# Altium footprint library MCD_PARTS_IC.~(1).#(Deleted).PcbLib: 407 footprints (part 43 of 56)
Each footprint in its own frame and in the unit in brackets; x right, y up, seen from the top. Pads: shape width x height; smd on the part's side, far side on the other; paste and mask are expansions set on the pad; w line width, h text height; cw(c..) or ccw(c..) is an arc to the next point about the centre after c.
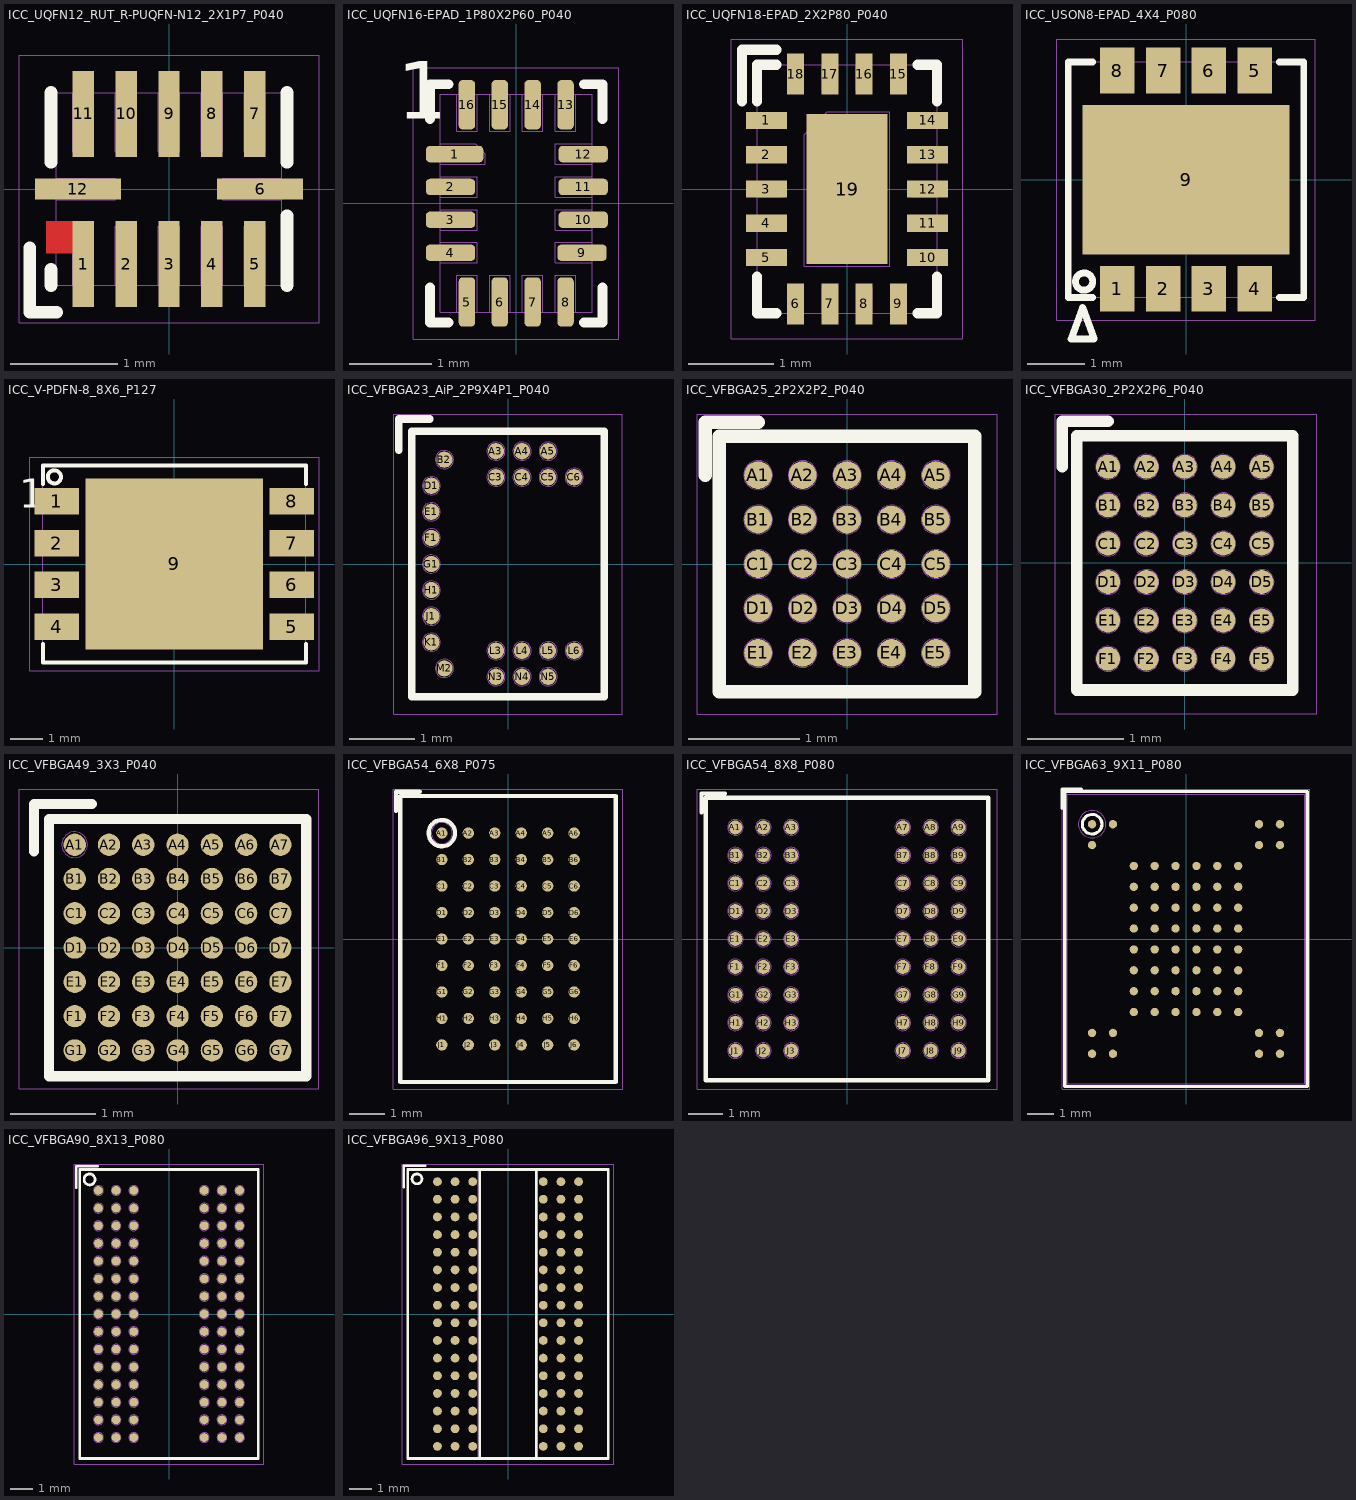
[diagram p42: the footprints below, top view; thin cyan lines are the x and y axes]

## ICC_UQFN12_RUT_R-PUQFN-N12_2X1P7_P040 [mm] "MCD-02643"
height 0.55
pads (12):
  rect 0.2x0.8 smd mask+0.05: 1(-0.8,-0.7) 2(-0.4,-0.7) 3(0,-0.7) 4(0.4,-0.7) 5(0.8,-0.7) 7(0.8,0.7) 8(0.4,0.7) 9(0,0.7) 10(-0.4,0.7) 11(-0.8,0.7)
  rect 0.8x0.2 smd mask+0.05: 6(0.85,0) 12(-0.85,0)
Top Layer:
  rectangle: -1.15,-0.6 -0.725,-0.3
Top Overlay:
  lines w0.12: -1.3,-0.55 -1.3,-1.15 -1.05,-1.15 ; -1.1,-0.9 -1.1,-0.75 ; -1.1,0.25 -1.1,0.9 ; 1.1,-0.9 1.1,-0.25 ; 1.1,0.25 1.1,0.9
M14-Top Assembly:
  lines w0.01: -1.05,-0.55 -0.9,-0.55 -0.9,-0.9 ; -1.05,-0.35 -0.7,-0.35 -0.7,-0.9 ; -1.05,-0.1 -0.5,-0.1 -0.5,0.1 -1.05,0.1 ; -0.9,0.9 -0.9,0.35 -0.7,0.35 -0.7,0.9 ; -0.5,-0.9 -0.5,-0.35 -0.3,-0.35 -0.3,-0.9 ; -0.5,0.9 -0.5,0.35 -0.3,0.35 -0.3,0.9 ; -0.1,-0.9 -0.1,-0.35 0.1,-0.35 0.1,-0.9 ; -0.1,0.9 -0.1,0.35 0.1,0.35 0.1,0.9 ; 0.3,-0.9 0.3,-0.35 0.5,-0.35 0.5,-0.9 ; 0.3,0.9 0.3,0.35 0.5,0.35 0.5,0.9 ; 0.7,-0.9 0.7,-0.35 0.9,-0.35 0.9,-0.9 ; 0.7,0.9 0.7,0.35 0.9,0.35 0.9,0.9 ; 1.05,0 1.05,-0.1 0.5,-0.1 0.5,0.1 1.05,0.1 ; -1.05,-0.9 1.05,-0.9 1.05,0.9 -1.05,0.9 -1.05,-0.9
  text "12" at -0.629,-0.213 h0.5
  text "11" at -0.983,0.479 h0.5
  text "7" at 0.696,0.484 h0.5
  text "6" at 0.948,-0.104 h0.5
  text "5" at 0.696,-0.798 h0.5
  text "1" at -0.859,-0.8 h0.5
  text "'.Designator'" at -2,-0.5 h0.75
M16-Top Courtyard:
  lines w0.01: -1.4,-1.25 1.4,-1.25 1.4,1.25 -1.4,1.25 -1.4,-1.25
3D body: height 0.13, standoff 0, extent -1.1,-0.1 -1.05,0.1
3D body: height 0.08, standoff 0, extent -1.1,-0.55 -1.05,-0.35
3D body: height 0.05, standoff 0, extent -1.1,-0.55 -0.9,-0.35
3D body: height 0.05, standoff 0, extent -0.9,-0.95 -0.7,-0.35
3D body: height 0.13, standoff 0, extent -0.9,-0.95 -0.7,-0.9
3D body: height 0.05, standoff 0, extent -0.9,0.35 -0.7,0.95
3D body: height 0.13, standoff 0, extent -0.9,0.9 -0.7,0.95
3D body: height 0.05, standoff 0, extent -1.1,-0.1 -0.5,0.1
3D body: height 0.13, standoff 0, extent -0.5,-0.95 -0.3,-0.9
3D body: height 0.05, standoff 0, extent -0.5,0.35 -0.3,0.95
3D body: height 0.13, standoff 0, extent -0.5,0.9 -0.3,0.95
3D body: height 0.05, standoff 0, extent -0.5,-0.95 -0.3,-0.35
3D body: height 0.13, standoff 0, extent -0.1,0.9 0.1,0.95
3D body: height 0.05, standoff 0, extent -0.1,-0.95 0.1,-0.35
3D body: height 0.05, standoff 0, extent -0.1,0.35 0.1,0.95
3D body: height 0.13, standoff 0, extent -0.1,-0.95 0.1,-0.9
3D body: height 0.05, standoff 0, extent 0.3,-0.95 0.5,-0.35
3D body: height 0.13, standoff 0, extent 0.3,-0.95 0.5,-0.9
3D body: height 0.13, standoff 0, extent 0.7,-0.95 0.9,-0.9
3D body: height 0.05, standoff 0, extent 0.7,-0.95 0.9,-0.35
3D body: height 0.13, standoff 0, extent 1.05,-0.1 1.1,0.1
3D body: height 0.05, standoff 0, extent 0.5,-0.1 1.1,0.1
3D body: height 0.05, standoff 0, extent 0.3,0.35 0.5,0.95
3D body: height 0.05, standoff 0, extent 0.7,0.35 0.9,0.95
3D body: height 0.13, standoff 0, extent 0.3,0.9 0.5,0.95
3D body: height 0.13, standoff 0, extent 0.7,0.9 0.9,0.95
3D body: height 0.55, standoff 0.05, extent -1.05,-0.9 1.05,0.9
3D body: height 0.56, standoff 0.55, extent -0.95,-0.8 -0.5,-0.35

## ICC_UQFN16-EPAD_1P80X2P60_P040 [mm]
height 0.55
pads (16):
  rrect50% 0.7x0.2 smd mask+0.05: 1(-0.75,0.6)
  rrect50% 0.6x0.2 smd mask+0.05: 2(-0.8,0.2) 3(-0.8,-0.2) 4(-0.8,-0.6) 9(0.8,-0.6) 10(0.815,-0.2) 11(0.815,0.2) 12(0.815,0.6)
  rrect50% 0.2x0.6 smd mask+0.05: 5(-0.6,-1.2) 6(-0.2,-1.2) 7(0.2,-1.2) 8(0.6,-1.2) 13(0.6,1.2) 14(0.2,1.2) 15(-0.2,1.2) 16(-0.6,1.2)
Top Overlay:
  lines w0.12: -1.05,-1.025 -1.05,-1.45 -0.825,-1.45 ; -1.05,1.025 -1.05,1.45 -0.825,1.45 ; 0.825,-1.45 1.05,-1.45 1.05,-1.025 ; 0.825,1.45 1.05,1.45 1.05,1.025
  text "1" at -1.45,0.8 h1.2
M14-Top Assembly:
  lines w0.01: -0.925,-0.725 -0.475,-0.725 -0.475,-0.475 -0.925,-0.475 ; -0.925,-0.325 -0.475,-0.325 -0.475,-0.075 -0.925,-0.075 ; -0.925,0.075 -0.475,0.075 -0.475,0.325 -0.925,0.325 ; -0.925,0.475 -0.375,0.475 -0.375,0.6 -0.5,0.725 -0.925,0.725 ; -0.725,-1.325 -0.725,-0.875 -0.475,-0.875 -0.475,-1.325 ; -0.725,1.325 -0.725,0.875 -0.475,0.875 -0.475,1.325 ; -0.325,-1.325 -0.325,-0.875 -0.075,-0.875 -0.075,-1.325 ; -0.325,1.325 -0.325,0.875 -0.075,0.875 -0.075,1.325 ; 0.075,-1.325 0.075,-0.875 0.325,-0.875 0.325,-1.325 ; 0.075,1.325 0.075,0.875 0.325,0.875 0.325,1.325 ; 0.475,-1.325 0.475,-0.875 0.725,-0.875 0.725,-1.325 ; 0.475,1.325 0.475,0.875 0.725,0.875 0.725,1.325 ; 0.925,-0.725 0.475,-0.725 0.475,-0.475 0.925,-0.475 ; 0.925,-0.325 0.475,-0.325 0.475,-0.075 0.925,-0.075 ; 0.925,0.075 0.475,0.075 0.475,0.325 0.925,0.325 ; 0.925,0.475 0.475,0.475 0.475,0.725 0.925,0.725 ; -1.05,1.45 -1.05,1.45 ; -1.05,1.45 -1.05,1.45 ; -1.05,-1.45 -1.05,-1.45 ; -0.925,-1.325 -0.925,1.325 0.925,1.325 0.925,-1.325 -0.925,-1.325
  text "13" at 0.425,0.975 h0.4
  text "16" at -0.775,0.975 h0.4
  text "8" at 0.525,-1.225 h0.4
  text "4" at -0.875,-0.725 h0.4
  text "12" at 0.525,0.475 h0.4
  text "9" at 0.7,-0.725 h0.4
  text "5" at -0.694,-1.221 h0.4
  text "1" at -0.844,0.475 h0.4
  text "'.Designator'" at -2,-0.5 h0.75
M16-Top Courtyard:
  lines w0.01: -1.25,-1.65 -1.25,1.65 1.25,1.65 1.25,-1.65 -1.25,-1.65
3D body "User Library-UQFN-16-0_4(Case 2_6mmx1_8mm Height 0_55mm).STEP": height 0.56, standoff 0, extent -0.91,-1.31 0.91,1.31

## ICC_UQFN18-EPAD_2X2P80_P040 [mm] "MCD-02300"
height 0.4
pads (19):
  rect 0.48x0.2 smd mask+0.05: 1(-0.94,0.8) 2(-0.94,0.4) 3(-0.94,0) 4(-0.94,-0.4) 5(-0.94,-0.8) 10(0.94,-0.8) 11(0.94,-0.4) 12(0.94,0) 13(0.94,0.4) 14(0.94,0.8)
  rect 0.2x0.48 smd mask+0.05: 6(-0.6,-1.34) 7(-0.2,-1.34) 8(0.2,-1.34) 9(0.6,-1.34) 15(0.6,1.34) 16(0.2,1.34) 17(-0.2,1.34) 18(-0.6,1.34)
  rect 0.95x1.75 smd mask+0.05: 19(0,0)
Top Overlay:
  lines w0.12: -1.225,1.025 -1.225,1.625 -0.825,1.625 ; -1.05,-1.025 -1.05,-1.45 -0.825,-1.45 ; -1.05,1.025 -1.05,1.45 -0.825,1.45 ; 0.825,-1.45 1.05,-1.45 1.05,-1.025 ; 0.825,1.45 1.05,1.45 1.05,1.025
M14-Top Assembly:
  lines w0.01: -1.05,-0.89 -0.75,-0.89 -0.75,-0.71 -1.05,-0.71 ; -1.05,-0.49 -0.75,-0.49 -0.75,-0.31 -1.05,-0.31 ; -1.05,-0.09 -0.75,-0.09 -0.75,0.09 -1.05,0.09 ; -1.05,0.31 -0.75,0.31 -0.75,0.49 -1.05,0.49 ; -1.05,0.71 -0.75,0.71 -0.75,0.89 -1.05,0.89 ; -0.69,1.45 -0.69,1.15 -0.51,1.15 -0.51,1.45 ; -0.687,-1.45 -0.687,-1.15 -0.507,-1.15 -0.507,-1.45 ; -0.29,1.45 -0.29,1.15 -0.11,1.15 -0.11,1.45 ; -0.287,-1.45 -0.287,-1.15 -0.107,-1.15 -0.107,-1.45 ; 0.11,1.45 0.11,1.15 0.29,1.15 0.29,1.45 ; 0.113,-1.45 0.113,-1.15 0.293,-1.15 0.293,-1.45 ; 0.51,1.45 0.51,1.15 0.69,1.15 0.69,1.45 ; 0.513,-1.45 0.513,-1.15 0.693,-1.15 0.693,-1.45 ; 1.05,-0.89 0.75,-0.89 0.75,-0.71 1.05,-0.71 ; 1.05,-0.49 0.75,-0.49 0.75,-0.31 1.05,-0.31 ; 1.05,-0.09 0.75,-0.09 0.75,0.09 1.05,0.09 ; 1.05,0.31 0.75,0.31 0.75,0.49 1.05,0.49 ; 1.05,0.71 0.75,0.71 0.75,0.89 1.05,0.89 ; -1.05,-1.45 1.05,-1.45 1.05,1.45 -1.05,1.45 ; -1.05,-1.45 -1.05,-1.45 ; -1.05,-1.45 -1.05,1.45 ; -1.05,1.45 -1.05,1.45 ; -1.05,1.45 -1.05,1.45 ; -0.5,-0.9 0.5,-0.9 0.5,0.9 -0.23,0.9 -0.5,0.63 -0.5,-0.9
  text "'.Designator'" at -1.803,-0.619 h0.75
  text "1" at -0.95,0.685 h0.4
  text "5" at -1,-0.915 h0.4
  text "10" at 0.675,-0.915 h0.4
  text "14" at 0.675,0.675 h0.4
  text "6" at -0.687,-1.425 h0.4
  text "9" at 0.513,-1.425 h0.4
  text "18" at -0.763,1.162 h0.4
  text "15" at 0.425,1.162 h0.4
  text "19" at -0.175,0.262 h0.4
M16-Top Courtyard:
  lines w0.01: -1.35,-1.75 1.35,-1.75 1.35,-1.725 1.35,1.725 1.35,1.75 -1.35,1.75 -1.35,1.725 -1.35,-1.725 -1.35,-1.75
3D body: height 0.41, standoff 0.4, extent -0.925,1.075 -0.675,1.325
3D body: height 0.05, standoff 0, extent -0.5,-0.9 0.5,0.9
3D body: height 0.4, standoff 0.05, extent -1.05,-1.45 1.05,1.45
3D body: height 0.05, standoff 0, extent 0.75,0.71 1.05,0.89
3D body: height 0.15, standoff 0, extent 1.05,0.71 1.1,0.89
3D body: height 0.05, standoff 0, extent 0.75,0.31 1.05,0.49
3D body: height 0.15, standoff 0, extent 1.05,0.31 1.1,0.49
3D body: height 0.05, standoff 0, extent 0.75,-0.09 1.05,0.09
3D body: height 0.15, standoff 0, extent 1.05,-0.09 1.1,0.09
3D body: height 0.05, standoff 0, extent 0.75,-0.49 1.05,-0.31
3D body: height 0.15, standoff 0, extent 1.05,-0.49 1.1,-0.31
3D body: height 0.05, standoff 0, extent 0.75,-0.89 1.05,-0.71
3D body: height 0.15, standoff 0, extent 1.05,-0.89 1.1,-0.71
3D body: height 0.05, standoff 0, extent 0.512,-1.45 0.692,-1.15
3D body: height 0.15, standoff 0, extent 0.512,-1.5 0.693,-1.45
3D body: height 0.05, standoff 0, extent 0.112,-1.45 0.292,-1.15
3D body: height 0.15, standoff 0, extent 0.112,-1.5 0.292,-1.45
3D body: height 0.05, standoff 0, extent -0.288,-1.45 -0.108,-1.15
3D body: height 0.15, standoff 0, extent -0.288,-1.5 -0.108,-1.45
3D body: height 0.05, standoff 0, extent -0.688,-1.45 -0.508,-1.15
3D body: height 0.15, standoff 0, extent -0.688,-1.5 -0.507,-1.45
3D body: height 0.05, standoff 0, extent -1.05,-0.89 -0.75,-0.71
3D body: height 0.15, standoff 0, extent -1.1,-0.89 -1.05,-0.71
3D body: height 0.05, standoff 0, extent -1.05,-0.49 -0.75,-0.31
3D body: height 0.15, standoff 0, extent -1.1,-0.49 -1.05,-0.31
3D body: height 0.05, standoff 0, extent -1.05,-0.09 -0.75,0.09
3D body: height 0.15, standoff 0, extent -1.1,-0.09 -1.05,0.09
3D body: height 0.05, standoff 0, extent -1.05,0.31 -0.75,0.49
3D body: height 0.15, standoff 0, extent -1.1,0.31 -1.05,0.49
3D body: height 0.05, standoff 0, extent -1.05,0.71 -0.75,0.89
3D body: height 0.15, standoff 0, extent -1.1,0.71 -1.05,0.89
3D body: height 0.05, standoff 0, extent 0.51,1.15 0.69,1.45
3D body: height 0.15, standoff 0, extent 0.51,1.45 0.69,1.5
3D body: height 0.05, standoff 0, extent 0.11,1.15 0.29,1.45
3D body: height 0.15, standoff 0, extent 0.11,1.45 0.29,1.5
3D body: height 0.05, standoff 0, extent -0.29,1.15 -0.11,1.45
3D body: height 0.15, standoff 0, extent -0.29,1.45 -0.11,1.5
3D body: height 0.05, standoff 0, extent -0.69,1.15 -0.51,1.45
3D body: height 0.15, standoff 0, extent -0.69,1.45 -0.51,1.5

## ICC_USON8-EPAD_4X4_P080 [mm]
height 0.6
pads (9):
  rect 0.6x0.8 smd paste+0 mask+0.05: 1(-1.2,-1.9) 2(-0.4,-1.9) 3(0.4,-1.9) 4(1.2,-1.9) 5(1.2,1.9) 6(0.4,1.9) 7(-0.4,1.9) 8(-1.2,1.9)
  rect 3.6x2.6 smd paste+0 mask+0.05: 9(0,0)
Top Overlay:
  circle w0.12: c-1.775,-1.775 r0.15
  lines w0.12: -1.625,-2.05 -2.05,-2.05 -2.05,2.05 -1.625,2.05 ; 1.625,-2.05 2.05,-2.05 2.05,2.05 1.625,2.05 ; -2,-2.775 -1.6,-2.775 -1.8,-2.225 -2,-2.775
M14-Top Assembly:
  lines w0.01: -1.375,-2.05 -1.375,-1.6 -1.025,-1.6 -1.025,-2.05 ; -1.375,2.05 -1.375,1.6 -1.025,1.6 -1.025,2.05 ; -0.575,-2.05 -0.575,-1.6 -0.225,-1.6 -0.225,-2.05 ; -0.575,2.05 -0.575,1.6 -0.225,1.6 -0.225,2.05 ; 0.225,-2.05 0.225,-1.6 0.575,-1.6 0.575,-2.05 ; 0.225,2.05 0.225,1.6 0.575,1.6 0.575,2.05 ; 1.025,-2.05 1.025,-1.6 1.375,-1.6 1.375,-2.05 ; 1.025,2.05 1.025,1.6 1.375,1.6 1.375,2.05 ; -2.05,-2.05 2.05,-2.05 2.05,2.05 -2.05,2.05 -2.05,-2.05 ; -1.55,-1.2 1.55,-1.2 1.55,1.2 -1.55,1.2 -1.55,-1.2
  text "'.Designator'" at -2,0.25 h0.75
  text "1" at -1.6,-2 h0.7
  text "4" at 1.425,-2 h0.7
  text "5" at 1.425,1.55 h0.7
  text "8" at -1.725,1.55 h0.7
  text "9" at -0.125,-0.2 h0.7
M16-Top Courtyard:
  lines w0.01: -2.25,-2.45 2.25,-2.45 2.25,2.45 -2.25,2.45 -2.25,-2.45
3D body: height 0.6, standoff 0, extent -2.05,-2.05 2.05,2.05
3D body "USON_8_4X4.STEP": height 0.59, standoff 0, extent -2,-2 2,2

## ICC_V-PDFN-8_8X6_P127 [mm]
height 1
pads (9):
  rect 1.35x0.8 smd mask+0.05: 1(-3.575,1.905) 2(-3.575,0.635) 3(-3.575,-0.635) 4(-3.575,-1.905) 5(3.575,-1.905) 6(3.575,-0.635) 7(3.575,0.635) 8(3.575,1.905)
  rect 5.4x5.2 smd mask+0.05: 9(0,0)
Top Overlay:
  circle w0.12: c-3.65,2.65 r0.2
  lines w0.12: -4,-2.425 -4,-3 4,-3 4,-2.425 ; -4,2.425 -4,3 4,3 4,2.425
  text "1" at -4.725,1.425 h1.5
M14-Top Assembly:
  circle w0.01: c-3.675,2.675 r0.2
  lines w0.01: -4,-2.16 -3.4,-2.16 -3.4,-1.65 -4,-1.65 ; -4,-0.89 -3.4,-0.89 -3.4,-0.38 -4,-0.38 ; -4,0.38 -3.4,0.38 -3.4,0.89 -4,0.89 ; -4,1.65 -3.4,1.65 -3.4,2.16 -4,2.16 ; 4,-2.16 3.4,-2.16 3.4,-1.65 4,-1.65 ; 4,-0.89 3.4,-0.89 3.4,-0.38 4,-0.38 ; 4,0.38 3.4,0.38 3.4,0.89 4,0.89 ; 4,1.65 3.4,1.65 3.4,2.16 4,2.16 ; -4,-3 -4,3 4,3 4,-3 -4,-3 ; -2.6,-2.4 -2.6,2.4 2.6,2.4 2.6,-2.4 -2.6,-2.4
  text "1" at -3.325,1.45 h1.5
  text "4" at -3.325,-2.375 h1.5
  text "5" at 2.675,-2.375 h1.5
  text "8" at 2.675,1.425 h1.5
  text "'.Designator'" at -2,-0.5 h0.75
M16-Top Courtyard:
  lines w0.01: -4.4,-3.25 4.4,-3.25 4.4,3.25 -4.4,3.25 -4.4,3.05 -4.4,-3.25
3D body: height 1, standoff 0, extent -4.005,-3.005 4.005,3.005
3D body "V-PDFN-8_8X6_.STEP": height 1.01, standoff 0, extent -4.025,-2.997 4.025,3.003

## ICC_VFBGA23_AiP_2P9X4P1_P040 [mm] "MCD-03321"
height 0.8
pads (23):
  round 0.25 smd mask+0.038: A3(-0.185,1.73) A4(0.215,1.73) A5(0.615,1.73) B2(-0.975,1.6) C3(-0.185,1.33) C4(0.215,1.33) C5(0.615,1.33) C6(1.015,1.33) D1(-1.175,1.2) E1(-1.175,0.8) F1(-1.175,0.4) G1(-1.175,0) H1(-1.175,-0.4) J1(-1.175,-0.8) K1(-1.175,-1.2) L3(-0.185,-1.33) L4(0.215,-1.33) L5(0.615,-1.33) L6(1.015,-1.33) M2(-0.975,-1.6) N3(-0.185,-1.73) N4(0.215,-1.73) N5(0.615,-1.73)
Top Overlay:
  lines w0.12: -1.675,1.75 -1.675,2.225 -1.2,2.225 ; -1.475,-2.035 1.475,-2.035 1.475,2.035 -1.475,2.035 -1.475,-2.035
M14-Top Assembly:
  circle w0.01: c1.015,1.33 r0.14
  circle w0.01: c0.615,1.33 r0.14
  circle w0.01: c0.215,1.33 r0.14
  circle w0.01: c-0.185,1.33 r0.14
  circle w0.01: c0.615,1.73 r0.14
  circle w0.01: c0.215,1.73 r0.14
  circle w0.01: c-0.185,1.73 r0.14
  circle w0.01: c1.015,-1.33 r0.14
  circle w0.01: c0.615,-1.33 r0.14
  circle w0.01: c0.215,-1.33 r0.14
  circle w0.01: c-0.185,-1.33 r0.14
  circle w0.01: c0.615,-1.73 r0.14
  circle w0.01: c0.215,-1.73 r0.14
  circle w0.01: c-0.185,-1.73 r0.14
  circle w0.01: c-0.975,-1.6 r0.14
  circle w0.01: c-0.975,1.6 r0.14
  circle w0.01: c-1.175,0 r0.14
  circle w0.01: c-1.175,0.4 r0.14
  circle w0.01: c-1.175,-0.4 r0.14
  circle w0.01: c-1.175,-0.8 r0.14
  circle w0.01: c-1.175,-1.2 r0.14
  circle w0.01: c-1.175,0.8 r0.14
  circle w0.01: c-1.175,1.2 r0.14
  lines w0.01: -1.475,-2.035 -1.475,2.035 1.475,2.035 1.475,-2.035 -1.475,-2.035
  text "A3" at -0.35,1.625 h0.3
  text "'.Designator'" at -2,-0.5 h0.75
M16-Top Courtyard:
  lines w0.01: -1.75,-2.3 1.75,-2.3 1.75,2.3 -1.75,2.3 -1.75,-2.3
3D body: height 0.26, standoff -0.02, extent 0.475,-1.87 0.755,-1.59
3D body: height 0.26, standoff -0.02, extent 0.075,-1.87 0.355,-1.59
3D body: height 0.26, standoff -0.02, extent -0.325,-1.87 -0.045,-1.59
3D body: height 0.26, standoff -0.02, extent 0.875,-1.47 1.155,-1.19
3D body: height 0.26, standoff -0.02, extent 0.475,-1.47 0.755,-1.19
3D body: height 0.26, standoff -0.02, extent 0.075,-1.47 0.355,-1.19
3D body: height 0.26, standoff -0.02, extent -0.325,-1.47 -0.045,-1.19
3D body: height 0.26, standoff -0.02, extent -1.115,-1.74 -0.835,-1.46
3D body: height 0.26, standoff -0.02, extent -1.315,-1.34 -1.035,-1.06
3D body: height 0.26, standoff -0.02, extent -1.315,-0.94 -1.035,-0.66
3D body: height 0.26, standoff -0.02, extent -1.315,-0.54 -1.035,-0.26
3D body: height 0.26, standoff -0.02, extent -1.315,-0.14 -1.035,0.14
3D body: height 0.26, standoff -0.02, extent -1.315,0.26 -1.035,0.54
3D body: height 0.26, standoff -0.02, extent -1.315,0.66 -1.035,0.94
3D body: height 0.26, standoff -0.02, extent -1.315,1.06 -1.035,1.34
3D body: height 0.26, standoff -0.02, extent 0.875,1.19 1.155,1.47
3D body: height 0.26, standoff -0.02, extent 0.475,1.19 0.755,1.47
3D body: height 0.26, standoff -0.02, extent 0.075,1.19 0.355,1.47
3D body: height 0.26, standoff -0.02, extent -0.325,1.19 -0.045,1.47
3D body: height 0.26, standoff -0.02, extent -1.115,1.46 -0.835,1.74
3D body: height 0.26, standoff -0.02, extent 0.475,1.59 0.755,1.87
3D body: height 0.26, standoff -0.02, extent 0.075,1.59 0.355,1.87
3D body: height 0.26, standoff -0.02, extent -0.325,1.59 -0.045,1.87
3D body: height 0.8, standoff 0.1, extent -1.5,-2.06 1.5,2.06
3D body: height 0.81, standoff 0.8, extent -1.124,1.45 -0.825,1.75

## ICC_VFBGA25_2P2X2P2_P040 [mm] "MCD-02719"
height 1
pads (25):
  round 0.25 smd mask+0.038: A1(-0.8,0.8) A2(-0.4,0.8) A3(0,0.8) A4(0.4,0.8) A5(0.8,0.8) B1(-0.8,0.4) B2(-0.4,0.4) B3(0,0.4) B4(0.4,0.4) B5(0.8,0.4) C1(-0.8,0) C2(-0.4,0) C3(0,0) C4(0.4,0) C5(0.8,0) D1(-0.8,-0.4) D2(-0.4,-0.4) D3(0,-0.4) D4(0.4,-0.4) D5(0.8,-0.4) E1(-0.8,-0.8) E2(-0.4,-0.8) E3(0,-0.8) E4(0.4,-0.8) E5(0.8,-0.8)
Top Overlay:
  lines w0.12: -1.275,0.8 -1.275,1.275 -0.8,1.275 ; -1.15,-1.15 1.15,-1.15 1.15,1.15 -1.15,1.15 -1.15,-1.15
M14-Top Assembly:
  circle w0.01: c0.8,0.8 r0.13
  circle w0.01: c0.4,0.8 r0.13
  circle w0.01: c0.8,0.4 r0.13
  circle w0.01: c0.4,0.4 r0.13
  circle w0.01: c0.8,0 r0.13
  circle w0.01: c0.4,0 r0.13
  circle w0.01: c0,0 r0.13
  circle w0.01: c0.8,-0.4 r0.13
  circle w0.01: c0.4,-0.4 r0.13
  circle w0.01: c0.8,-0.8 r0.13
  circle w0.01: c0.4,-0.8 r0.13
  circle w0.01: c0,-0.8 r0.13
  circle w0.01: c0,-0.4 r0.13
  circle w0.01: c0,0.4 r0.13
  circle w0.01: c0,0.8 r0.13
  circle w0.01: c-0.4,0.4 r0.13
  circle w0.01: c-0.4,0 r0.13
  circle w0.01: c-0.4,-0.8 r0.13
  circle w0.01: c-0.4,-0.4 r0.13
  circle w0.01: c-0.4,0.8 r0.13
  circle w0.01: c-0.8,0.4 r0.13
  circle w0.01: c-0.8,-0.4 r0.13
  circle w0.01: c-0.8,0 r0.13
  circle w0.01: c-0.8,-0.8 r0.13
  circle w0.01: c-0.8,0.8 r0.13
  lines w0.01: -1.15,-1.15 1.15,-1.15 1.15,1.15 -1.15,1.15 -1.15,-1.15
  text "A5" at 0.66,0.71 h0.15
  text "E5" at 0.676,-0.89 h0.15
  text "A1" at -0.907,0.71 h0.15
  text "E1" at -0.892,-0.89 h0.15
  text "'.Designator'" at -2,-0.5 h0.75
M16-Top Courtyard:
  lines w0.01: -1.35,-1.35 -1.35,1.35 1.35,1.35 1.35,-1.35 -1.35,-1.35
3D body: height 0.26, standoff -0.02, extent 0.66,-0.94 0.94,-0.66
3D body: height 0.26, standoff -0.02, extent 0.26,-0.94 0.54,-0.66
3D body: height 0.26, standoff -0.02, extent -0.14,-0.94 0.14,-0.66
3D body: height 0.26, standoff -0.02, extent -0.54,-0.94 -0.26,-0.66
3D body: height 0.26, standoff -0.02, extent -0.94,-0.94 -0.66,-0.66
3D body: height 0.26, standoff -0.02, extent 0.66,-0.54 0.94,-0.26
3D body: height 0.26, standoff -0.02, extent 0.26,-0.54 0.54,-0.26
3D body: height 0.26, standoff -0.02, extent -0.14,-0.54 0.14,-0.26
3D body: height 0.26, standoff -0.02, extent -0.54,-0.54 -0.26,-0.26
3D body: height 0.26, standoff -0.02, extent -0.94,-0.54 -0.66,-0.26
3D body: height 0.26, standoff -0.02, extent 0.66,-0.14 0.94,0.14
3D body: height 0.26, standoff -0.02, extent 0.26,-0.14 0.54,0.14
3D body: height 0.26, standoff -0.02, extent -0.14,-0.14 0.14,0.14
3D body: height 0.26, standoff -0.02, extent -0.54,-0.14 -0.26,0.14
3D body: height 0.26, standoff -0.02, extent -0.94,-0.14 -0.66,0.14
3D body: height 0.26, standoff -0.02, extent 0.66,0.26 0.94,0.54
3D body: height 0.26, standoff -0.02, extent 0.26,0.26 0.54,0.54
3D body: height 0.26, standoff -0.02, extent -0.14,0.26 0.14,0.54
3D body: height 0.26, standoff -0.02, extent -0.54,0.26 -0.26,0.54
3D body: height 0.26, standoff -0.02, extent -0.94,0.26 -0.66,0.54
3D body: height 0.26, standoff -0.02, extent 0.66,0.66 0.94,0.94
3D body: height 0.26, standoff -0.02, extent 0.26,0.66 0.54,0.94
3D body: height 0.26, standoff -0.02, extent -0.14,0.66 0.14,0.94
3D body: height 0.26, standoff -0.02, extent -0.54,0.66 -0.26,0.94
3D body: height 1.01, standoff 1, extent -0.95,0.65 -0.65,0.95
3D body: height 1, standoff 0.22, extent -1.15,-1.15 1.15,1.15
3D body: height 0.26, standoff -0.02, extent -0.94,0.66 -0.66,0.94

## ICC_VFBGA30_2P2X2P6_P040 [mm] "MCD-03321"
height 0.9
pads (30):
  round 0.25 smd mask+0.038: A1(-0.8,1) A2(-0.4,1) A3(0,1) A4(0.4,1) A5(0.8,1) B1(-0.8,0.6) B2(-0.4,0.6) B3(0,0.6) B4(0.4,0.6) B5(0.8,0.6) C1(-0.8,0.2) C2(-0.4,0.2) C3(0,0.2) C4(0.4,0.2) C5(0.8,0.2) D1(-0.8,-0.2) D2(-0.4,-0.2) D3(0,-0.2) D4(0.4,-0.2) D5(0.8,-0.2) E1(-0.8,-0.6) E2(-0.4,-0.6) E3(0,-0.6) E4(0.4,-0.6) E5(0.8,-0.6) F1(-0.8,-1) F2(-0.4,-1) F3(0,-1) F4(0.4,-1) F5(0.8,-1)
Top Overlay:
  lines w0.12: -1.275,1 -1.275,1.475 -0.8,1.475 ; -1.125,-1.325 -1.125,1.325 1.125,1.325 1.125,-1.325 -1.125,-1.325
M14-Top Assembly:
  circle w0.01: c-0.8,1 r0.13
  circle w0.01: c-0.8,-0.6 r0.13
  circle w0.01: c-0.8,0.2 r0.13
  circle w0.01: c-0.8,-0.2 r0.13
  circle w0.01: c-0.8,0.6 r0.13
  circle w0.01: c-0.4,1 r0.13
  circle w0.01: c-0.4,-0.2 r0.13
  circle w0.01: c-0.4,-0.6 r0.13
  circle w0.01: c-0.4,0.2 r0.13
  circle w0.01: c-0.4,0.6 r0.13
  circle w0.01: c0,1 r0.13
  circle w0.01: c0,0.6 r0.13
  circle w0.01: c0,-0.2 r0.13
  circle w0.01: c0,-0.6 r0.13
  circle w0.01: c0.4,-0.6 r0.13
  circle w0.01: c0.8,-0.6 r0.13
  circle w0.01: c0.4,-0.2 r0.13
  circle w0.01: c0.8,-0.2 r0.13
  circle w0.01: c0,0.2 r0.13
  circle w0.01: c0.4,0.2 r0.13
  circle w0.01: c0.8,0.2 r0.13
  circle w0.01: c0.4,0.6 r0.13
  circle w0.01: c0.8,0.6 r0.13
  circle w0.01: c0.4,1 r0.13
  circle w0.01: c0.8,1 r0.13
  circle w0.01: c-0.8,-1 r0.13
  circle w0.01: c-0.4,-1 r0.13
  circle w0.01: c0,-1 r0.13
  circle w0.01: c0.4,-1 r0.13
  circle w0.01: c0.8,-1 r0.13
  lines w0.01: -1.125,-1.325 -1.125,1.325 1.125,1.325 1.125,-1.325 -1.125,-1.325
  text "'.Designator'" at -2,-0.5 h0.75
  text "A1" at -0.907,0.91 h0.15
  text "A5" at 0.66,0.91 h0.15
  text "F1" at -0.892,-1.09 h0.15
  text "F5" at 0.676,-1.09 h0.15
M16-Top Courtyard:
  lines w0.01: -1.35,-1.575 1.375,-1.575 1.375,1.55 -1.35,1.55 -1.35,-1.575
3D body: height 0.26, standoff -0.02, extent -0.94,0.86 -0.66,1.14
3D body: height 0.9, standoff 0.22, extent -1.125,-1.325 1.125,1.325
3D body: height 0.91, standoff 0.9, extent -0.949,0.85 -0.65,1.15
3D body: height 0.26, standoff -0.02, extent -0.54,0.86 -0.26,1.14
3D body: height 0.26, standoff -0.02, extent -0.14,0.86 0.14,1.14
3D body: height 0.26, standoff -0.02, extent 0.26,0.86 0.54,1.14
3D body: height 0.26, standoff -0.02, extent 0.66,0.86 0.94,1.14
3D body: height 0.26, standoff -0.02, extent -0.94,0.46 -0.66,0.74
3D body: height 0.26, standoff -0.02, extent -0.54,0.46 -0.26,0.74
3D body: height 0.26, standoff -0.02, extent -0.14,0.46 0.14,0.74
3D body: height 0.26, standoff -0.02, extent 0.26,0.46 0.54,0.74
3D body: height 0.26, standoff -0.02, extent 0.66,0.46 0.94,0.74
3D body: height 0.26, standoff -0.02, extent -0.94,0.06 -0.66,0.34
3D body: height 0.26, standoff -0.02, extent -0.54,0.06 -0.26,0.34
3D body: height 0.26, standoff -0.02, extent -0.14,0.06 0.14,0.34
3D body: height 0.26, standoff -0.02, extent 0.26,0.06 0.54,0.34
3D body: height 0.26, standoff -0.02, extent 0.66,0.06 0.94,0.34
3D body: height 0.26, standoff -0.02, extent -0.94,-0.34 -0.66,-0.06
3D body: height 0.26, standoff -0.02, extent -0.54,-0.34 -0.26,-0.06
3D body: height 0.26, standoff -0.02, extent -0.14,-0.34 0.14,-0.06
3D body: height 0.26, standoff -0.02, extent 0.26,-0.34 0.54,-0.06
3D body: height 0.26, standoff -0.02, extent 0.66,-0.34 0.94,-0.06
3D body: height 0.26, standoff -0.02, extent -0.94,-0.74 -0.66,-0.46
3D body: height 0.26, standoff -0.02, extent -0.54,-0.74 -0.26,-0.46
3D body: height 0.26, standoff -0.02, extent -0.14,-0.74 0.14,-0.46
3D body: height 0.26, standoff -0.02, extent 0.26,-0.74 0.54,-0.46
3D body: height 0.26, standoff -0.02, extent 0.66,-0.74 0.94,-0.46
3D body: height 0.26, standoff -0.02, extent -0.94,-1.14 -0.66,-0.86
3D body: height 0.26, standoff -0.02, extent -0.54,-1.14 -0.26,-0.86
3D body: height 0.26, standoff -0.02, extent -0.14,-1.14 0.14,-0.86
3D body: height 0.26, standoff -0.02, extent 0.26,-1.14 0.54,-0.86
3D body: height 0.26, standoff -0.02, extent 0.66,-1.14 0.94,-0.86

## ICC_VFBGA49_3X3_P040 [mm] "MCD-02213"
height 1
pads (49):
  round 0.26 smd mask+0.03: A1(-1.2,1.2) A2(-0.8,1.2) A3(-0.4,1.2) A4(0,1.2) A5(0.4,1.2) A6(0.8,1.2) A7(1.2,1.2) B1(-1.2,0.8) B2(-0.8,0.8) B3(-0.4,0.8) B4(0,0.8) B5(0.4,0.8) B6(0.8,0.8) B7(1.2,0.8) C1(-1.2,0.4) C2(-0.8,0.4) C3(-0.4,0.4) C4(0,0.4) C5(0.4,0.4) C6(0.8,0.4) C7(1.2,0.4) D1(-1.2,0) D2(-0.8,0) D3(-0.4,0) D4(0,0) D5(0.4,0) D6(0.8,0) D7(1.2,0) E1(-1.2,-0.4) E2(-0.8,-0.4) E3(-0.4,-0.4) E4(0,-0.4) E5(0.4,-0.4) E6(0.8,-0.4) E7(1.2,-0.4) F1(-1.2,-0.8) F2(-0.8,-0.8) F3(-0.4,-0.8) F4(0,-0.8) F5(0.4,-0.8) F6(0.8,-0.8) F7(1.2,-0.8) G1(-1.2,-1.2) G2(-0.8,-1.2) G3(-0.4,-1.2) G4(0,-1.2) G5(0.4,-1.2) G6(0.8,-1.2) G7(1.2,-1.2)
Top Overlay:
  lines w0.12: -1.675,1.125 -1.675,1.675 -1,1.675 ; -1.5,-1.5 -1.5,1.5 1.5,1.5 1.5,-1.5 -1.5,-1.5
M14-Top Assembly:
  circle w0.01: c-1.2,1.2 r0.15
  lines w0.01: -1.5,-1.5 1.5,-1.5 1.5,1.5 -1.5,1.5 -1.5,-1.5
  text "'.Designator'" at 0,0 h0.75
  text "A1" at -1.45,1.05 h0.5
M16-Top Courtyard:
  lines w0.01: -1.85,-1.65 -1.85,1.85 1.65,1.85 1.65,-1.65 -1.85,-1.65
3D body: height 1, standoff 0, extent -1.5,-1.5 1.5,1.5
3D body: height 1.01, standoff 1, extent -1.423,0.826 -0.825,1.425

## ICC_VFBGA54_6X8_P075 [mm]
height 1
pads (54):
  round 0.32 smd mask+0.05: A1(-1.875,3) A2(-1.125,3) A3(-0.375,3) A4(0.375,3) A5(1.125,3) A6(1.875,3) B1(-1.875,2.25) B2(-1.125,2.25) B3(-0.375,2.25) B4(0.375,2.25) B5(1.125,2.25) B6(1.875,2.25) C1(-1.875,1.5) C2(-1.125,1.5) C3(-0.375,1.5) C4(0.375,1.5) C5(1.125,1.5) C6(1.875,1.5) D1(-1.875,0.75) D2(-1.125,0.75) D3(-0.375,0.75) D4(0.375,0.75) D5(1.125,0.75) D6(1.875,0.75) E1(-1.875,0) E2(-1.125,0) E3(-0.375,0) E4(0.375,0) E5(1.125,0) E6(1.875,0) F1(-1.875,-0.75) F2(-1.125,-0.75) F3(-0.375,-0.75) F4(0.375,-0.75) F5(1.125,-0.75) F6(1.875,-0.75) G1(-1.875,-1.5) G2(-1.125,-1.5) G3(-0.375,-1.5) G4(0.375,-1.5) G5(1.125,-1.5) G6(1.875,-1.5) H1(-1.875,-2.25) H2(-1.125,-2.25) H3(-0.375,-2.25) H4(0.375,-2.25) H5(1.125,-2.25) H6(1.875,-2.25) J1(-1.875,-3) J2(-1.125,-3) J3(-0.375,-3) J4(0.375,-3) J5(1.125,-3) J6(1.875,-3)
Top Overlay:
  circle w0.12: c-1.875,3 r0.375
  lines w0.12: -3.175,3.625 -3.175,4.175 -2.5,4.175 ; -3.05,-4.05 -3.05,4.05 3.05,4.05 3.05,-4.05 -3.05,-4.05
M14-Top Assembly:
  circle w0.01: c-1.875,3 r0.3
  lines w0.01: -3.05,-4.05 -3.05,4.05 3.05,4.05 3.05,-4.05 -3.05,-4.05
  text "'.Designator'" at -2,-0.5 h0.75
  text "A1" at -2.375,2.7 h1
M16-Top Courtyard:
  lines w0.01: -3.25,-4.25 -3.25,4.25 3.25,4.25 3.25,-4.25 -3.25,-4.25
3D body: height 1, standoff 0, extent -3.055,-4.055 3.055,4.055
3D body: height 1.01, standoff 1, extent -2.173,2.701 -1.575,3.299

## ICC_VFBGA54_8X8_P080 [mm] "MCD-04313"
height 1
pads (54):
  round 0.4 smd mask+0.05: A1(-3.2,3.2) A2(-2.4,3.2) A3(-1.6,3.2) A7(1.6,3.2) A8(2.4,3.2) A9(3.2,3.2) B1(-3.2,2.4) B2(-2.4,2.4) B3(-1.6,2.4) B7(1.6,2.4) B8(2.4,2.4) B9(3.2,2.4) C1(-3.2,1.6) C2(-2.4,1.6) C3(-1.6,1.6) C7(1.6,1.6) C8(2.4,1.6) C9(3.2,1.6) D1(-3.2,0.8) D2(-2.4,0.8) D3(-1.6,0.8) D7(1.6,0.8) D8(2.4,0.8) D9(3.2,0.8) E1(-3.2,0) E2(-2.4,0) E3(-1.6,0) E7(1.6,0) E8(2.4,0) E9(3.2,0) F1(-3.2,-0.8) F2(-2.4,-0.8) F3(-1.6,-0.8) F7(1.6,-0.8) F8(2.4,-0.8) F9(3.2,-0.8) G1(-3.2,-1.6) G2(-2.4,-1.6) G3(-1.6,-1.6) G7(1.6,-1.6) G8(2.4,-1.6) G9(3.2,-1.6) H1(-3.2,-2.4) H2(-2.4,-2.4) H3(-1.6,-2.4) H7(1.6,-2.4) H8(2.4,-2.4) H9(3.2,-2.4) J1(-3.2,-3.2) J2(-2.4,-3.2) J3(-1.6,-3.2) J7(1.6,-3.2) J8(2.4,-3.2) J9(3.2,-3.2)
Top Overlay:
  lines w0.12: -4.175,3.625 -4.175,4.175 -3.5,4.175 ; -4.05,-4.05 4.05,-4.05 4.05,4.05 -4.05,4.05 -4.05,-4.05
M14-Top Assembly:
  circle w0.01: c-3.2,3.2 r0.225
  circle w0.01: c-2.4,3.2 r0.225
  circle w0.01: c-1.6,3.2 r0.225
  circle w0.01: c1.6,3.2 r0.225
  circle w0.01: c2.4,3.2 r0.225
  circle w0.01: c3.2,3.2 r0.225
  circle w0.01: c-3.2,2.4 r0.225
  circle w0.01: c-2.4,2.4 r0.225
  circle w0.01: c-1.6,2.4 r0.225
  circle w0.01: c1.6,2.4 r0.225
  circle w0.01: c2.4,2.4 r0.225
  circle w0.01: c3.2,2.4 r0.225
  circle w0.01: c-3.2,2.4 r0.225
  circle w0.01: c-2.4,2.4 r0.225
  circle w0.01: c-1.6,2.4 r0.225
  circle w0.01: c1.6,2.4 r0.225
  circle w0.01: c2.4,2.4 r0.225
  circle w0.01: c3.2,2.4 r0.225
  circle w0.01: c-3.2,1.6 r0.225
  circle w0.01: c-2.4,1.6 r0.225
  circle w0.01: c-1.6,1.6 r0.225
  circle w0.01: c1.6,1.6 r0.225
  circle w0.01: c2.4,1.6 r0.225
  circle w0.01: c3.2,1.6 r0.225
  circle w0.01: c-3.2,0.8 r0.225
  circle w0.01: c-2.4,0.8 r0.225
  circle w0.01: c-1.6,0.8 r0.225
  circle w0.01: c1.6,0.8 r0.225
  circle w0.01: c2.4,0.8 r0.225
  circle w0.01: c3.2,0.8 r0.225
  circle w0.01: c-3.2,0 r0.225
  circle w0.01: c-2.4,0 r0.225
  circle w0.01: c-1.6,0 r0.225
  circle w0.01: c1.6,0 r0.225
  circle w0.01: c2.4,0 r0.225
  circle w0.01: c3.2,0 r0.225
  circle w0.01: c-3.2,-0.8 r0.225
  circle w0.01: c-2.4,-0.8 r0.225
  circle w0.01: c-1.6,-0.8 r0.225
  circle w0.01: c1.6,-0.8 r0.225
  circle w0.01: c2.4,-0.8 r0.225
  circle w0.01: c3.2,-0.8 r0.225
  circle w0.01: c-3.2,-1.6 r0.225
  circle w0.01: c-2.4,-1.6 r0.225
  circle w0.01: c-1.6,-1.6 r0.225
  circle w0.01: c1.6,-1.6 r0.225
  circle w0.01: c2.4,-1.6 r0.225
  circle w0.01: c3.2,-1.6 r0.225
  circle w0.01: c-3.2,-2.4 r0.225
  circle w0.01: c-2.4,-2.4 r0.225
  circle w0.01: c-1.6,-2.4 r0.225
  circle w0.01: c1.6,-2.4 r0.225
  circle w0.01: c2.4,-2.4 r0.225
  circle w0.01: c3.2,-2.4 r0.225
  circle w0.01: c-3.2,-3.2 r0.225
  circle w0.01: c-2.4,-3.2 r0.225
  circle w0.01: c-1.6,-3.2 r0.225
  circle w0.01: c1.6,-3.2 r0.225
  circle w0.01: c2.4,-3.2 r0.225
  circle w0.01: c3.2,-3.2 r0.225
  lines w0.01: -4.05,-4.05 4.05,-4.05 4.05,4.05 -4.05,4.05 -4.05,-4.05
  text "A1" at -3.75,3.051 h1
  text "'.Designator'" at -2,-0.5 h0.75
M16-Top Courtyard:
  lines w0.01: -4.3,-4.3 4.3,-4.3 4.3,4.3 -4.3,4.3 -4.3,-4.3
3D body: height 1.01, standoff 1, extent -3.55,3.051 -2.95,3.651
3D body: height 1, standoff 0.25, extent -4.05,-4.055 4.05,4.055
3D body: height 0.45, standoff 0, extent -3.425,2.975 -2.975,3.425
3D body: height 0.45, standoff 0, extent -2.625,2.975 -2.175,3.425
3D body: height 0.45, standoff 0, extent -1.825,2.975 -1.375,3.425
3D body: height 0.45, standoff 0, extent 1.375,2.975 1.825,3.425
3D body: height 0.45, standoff 0, extent 2.175,2.975 2.625,3.425
3D body: height 0.45, standoff 0, extent 2.975,2.975 3.425,3.425
3D body: height 0.45, standoff 0, extent -3.425,2.175 -2.975,2.625
3D body: height 0.45, standoff 0, extent -2.625,2.175 -2.175,2.625
3D body: height 0.45, standoff 0, extent -1.825,2.175 -1.375,2.625
3D body: height 0.45, standoff 0, extent 1.375,2.175 1.825,2.625
3D body: height 0.45, standoff 0, extent 2.175,2.175 2.625,2.625
3D body: height 0.45, standoff 0, extent 2.975,2.175 3.425,2.625
3D body: height 0.45, standoff 0, extent -3.425,1.375 -2.975,1.825
3D body: height 0.45, standoff 0, extent -2.625,1.375 -2.175,1.825
3D body: height 0.45, standoff 0, extent -1.825,1.375 -1.375,1.825
3D body: height 0.45, standoff 0, extent 1.375,1.375 1.825,1.825
3D body: height 0.45, standoff 0, extent 2.175,1.375 2.625,1.825
3D body: height 0.45, standoff 0, extent 2.975,1.375 3.425,1.825
3D body: height 0.45, standoff 0, extent -3.425,0.575 -2.975,1.025
3D body: height 0.45, standoff 0, extent -2.625,0.575 -2.175,1.025
3D body: height 0.45, standoff 0, extent -1.825,0.575 -1.375,1.025
3D body: height 0.45, standoff 0, extent 1.375,0.575 1.825,1.025
3D body: height 0.45, standoff 0, extent 2.175,0.575 2.625,1.025
3D body: height 0.45, standoff 0, extent 2.975,0.575 3.425,1.025
3D body: height 0.45, standoff 0, extent -3.425,-0.225 -2.975,0.225
3D body: height 0.45, standoff 0, extent -2.625,-0.225 -2.175,0.225
3D body: height 0.45, standoff 0, extent -1.825,-0.225 -1.375,0.225
3D body: height 0.45, standoff 0, extent 1.375,-0.225 1.825,0.225
3D body: height 0.45, standoff 0, extent 2.175,-0.225 2.625,0.225
3D body: height 0.45, standoff 0, extent 2.975,-0.225 3.425,0.225
3D body: height 0.45, standoff 0, extent -3.425,-1.025 -2.975,-0.575
3D body: height 0.45, standoff 0, extent -2.625,-1.025 -2.175,-0.575
3D body: height 0.45, standoff 0, extent -1.825,-1.025 -1.375,-0.575
3D body: height 0.45, standoff 0, extent 1.375,-1.025 1.825,-0.575
3D body: height 0.45, standoff 0, extent 2.175,-1.025 2.625,-0.575
3D body: height 0.45, standoff 0, extent 2.975,-1.025 3.425,-0.575
3D body: height 0.45, standoff 0, extent -3.425,-1.825 -2.975,-1.375
3D body: height 0.45, standoff 0, extent -2.625,-1.825 -2.175,-1.375
3D body: height 0.45, standoff 0, extent -1.825,-1.825 -1.375,-1.375
3D body: height 0.45, standoff 0, extent 1.375,-1.825 1.825,-1.375
3D body: height 0.45, standoff 0, extent 2.175,-1.825 2.625,-1.375
3D body: height 0.45, standoff 0, extent 2.975,-1.825 3.425,-1.375
3D body: height 0.45, standoff 0, extent -3.425,-2.625 -2.975,-2.175
3D body: height 0.45, standoff 0, extent -2.625,-2.625 -2.175,-2.175
3D body: height 0.45, standoff 0, extent -1.825,-2.625 -1.375,-2.175
3D body: height 0.45, standoff 0, extent 1.375,-2.625 1.825,-2.175
3D body: height 0.45, standoff 0, extent 2.175,-2.625 2.625,-2.175
3D body: height 0.45, standoff 0, extent 2.975,-2.625 3.425,-2.175
3D body: height 0.45, standoff 0, extent -3.425,-3.425 -2.975,-2.975
3D body: height 0.45, standoff 0, extent -2.625,-3.425 -2.175,-2.975
3D body: height 0.45, standoff 0, extent -1.825,-3.425 -1.375,-2.975
3D body: height 0.45, standoff 0, extent 1.375,-3.425 1.825,-2.975
3D body: height 0.45, standoff 0, extent 2.175,-3.425 2.625,-2.975
3D body: height 0.45, standoff 0, extent 2.975,-3.425 3.425,-2.975

## ICC_VFBGA63_9X11_P080 [mm]
height 1
pads (63):
  round 0.32 smd mask+0.05: A1(-3.6,4.4) A2(-2.8,4.4) A9(2.8,4.4) A10(3.6,4.4) B1(-3.6,3.6) B9(2.8,3.6) B10(3.6,3.6) C3(-2,2.8) C4(-1.2,2.8) C5(-0.4,2.8) C6(0.4,2.8) C7(1.2,2.8) C8(2,2.8) D3(-2,2) D4(-1.2,2) D5(-0.4,2) D6(0.4,2) D7(1.2,2) D8(2,2) E3(-2,1.2) E4(-1.2,1.2) E5(-0.4,1.2) E6(0.4,1.2) E7(1.2,1.2) E8(2,1.2) F3(-2,0.4) F4(-1.2,0.4) F5(-0.4,0.4) F6(0.4,0.4) F7(1.2,0.4) F8(2,0.4) G3(-2,-0.4) G4(-1.2,-0.4) G5(-0.4,-0.4) G6(0.4,-0.4) G7(1.2,-0.4) G8(2,-0.4) H3(-2,-1.2) H4(-1.2,-1.2) H5(-0.4,-1.2) H6(0.4,-1.2) H7(1.2,-1.2) H8(2,-1.2) J3(-2,-2) J4(-1.2,-2) J5(-0.4,-2) J6(0.4,-2) J7(1.2,-2) J8(2,-2) K3(-2,-2.8) K4(-1.2,-2.8) K5(-0.4,-2.8) K6(0.4,-2.8) K7(1.2,-2.8) K8(2,-2.8) L1(-3.6,-3.6) L2(-2.8,-3.6) L9(2.8,-3.6) L10(3.6,-3.6) M1(-3.6,-4.4) M2(-2.8,-4.4) M9(2.8,-4.4) M10(3.6,-4.4)
Top Overlay:
  circle w0.12: c-3.6,4.4 r0.375
  lines w0.12: -4.75,5 -4.75,5.75 -4,5.75 ; -4.65,-5.65 4.65,-5.65 4.65,5.65 4.325,5.65 -4.65,5.65 -4.65,-5.65
M14-Top Assembly:
  circle w0.01: c-3.6,4.4 r0.526
  lines w0.01: -4.55,-5.55 4.55,-5.55 4.55,5.55 -4.55,5.55 -4.55,-5.55
  text "A1" at -4.125,4.1 h1
  text "'.Designator'" at -2,-0.5 h0.75
M16-Top Courtyard:
  lines w0.01: -4.75,-5.75 4.75,-5.75 4.75,5.75 -4.75,5.75 -4.75,-5.75
3D body "VFBGA63_9X11_P080.STEP": height 1.24, standoff 0, extent -4.5,-5.5 4.5,5.5
3D body: height 1, standoff 0, extent -4.555,-5.555 4.555,5.555

## ICC_VFBGA90_8X13_P080 [mm] "B5__Pb Free"
height 1
pads (90):
  round 0.4 smd mask+0.05: A1(-3.2,5.6) A2(-2.4,5.6) A3(-1.6,5.6) A7(1.6,5.6) A8(2.4,5.6) A9(3.2,5.6) B1(-3.2,4.8) B2(-2.4,4.8) B3(-1.6,4.8) B7(1.6,4.8) B8(2.4,4.8) B9(3.2,4.8) C1(-3.2,4) C2(-2.4,4) C3(-1.6,4) C7(1.6,4) C8(2.4,4) C9(3.2,4) D1(-3.2,3.2) D2(-2.4,3.2) D3(-1.6,3.2) D7(1.6,3.2) D8(2.4,3.2) D9(3.2,3.2) E1(-3.2,2.4) E2(-2.4,2.4) E3(-1.6,2.4) E7(1.6,2.4) E8(2.4,2.4) E9(3.2,2.4) F1(-3.2,1.6) F2(-2.4,1.6) F3(-1.6,1.6) F7(1.6,1.6) F8(2.4,1.6) F9(3.2,1.6) G1(-3.2,0.8) G2(-2.4,0.8) G3(-1.6,0.8) G7(1.6,0.8) G8(2.4,0.8) G9(3.2,0.8) H1(-3.2,0) H2(-2.4,0) H3(-1.6,0) H7(1.6,0) H8(2.4,0) H9(3.2,0) J1(-3.2,-0.8) J2(-2.4,-0.8) J3(-1.6,-0.8) J7(1.6,-0.8) J8(2.4,-0.8) J9(3.2,-0.8) K1(-3.2,-1.6) K2(-2.4,-1.6) K3(-1.6,-1.6) K7(1.6,-1.6) K8(2.4,-1.6) K9(3.2,-1.6) L1(-3.2,-2.4) L2(-2.4,-2.4) L3(-1.6,-2.4) L7(1.6,-2.4) L8(2.4,-2.4) L9(3.2,-2.4) M1(-3.2,-3.2) M2(-2.4,-3.2) M3(-1.6,-3.2) M7(1.6,-3.2) M8(2.4,-3.2) M9(3.2,-3.2) N1(-3.2,-4) N2(-2.4,-4) N3(-1.6,-4) N7(1.6,-4) N8(2.4,-4) N9(3.2,-4) P1(-3.2,-4.8) P2(-2.4,-4.8) P3(-1.6,-4.8) P7(1.6,-4.8) P8(2.4,-4.8) P9(3.2,-4.8) R1(-3.2,-5.6) R2(-2.4,-5.6) R3(-1.6,-5.6) R7(1.6,-5.6) R8(2.4,-5.6) R9(3.2,-5.6)
Top Overlay:
  circle w0.12: c-3.6,6.1 r0.25
  lines w0.12: -4.2,5.725 -4.2,6.7 -3.225,6.7 ; -4.05,-6.55 4.05,-6.55 4.05,6.55 -4.05,6.55 -4.05,-6.55
M14-Top Assembly:
  circle w0.01: c-3.6,6.1 r0.25
  circle w0.01: c-3.2,-2.4 r0.225
  circle w0.01: c-2.4,-2.4 r0.225
  circle w0.01: c-1.6,-2.4 r0.225
  circle w0.01: c3.2,-2.4 r0.225
  circle w0.01: c2.4,-2.4 r0.225
  circle w0.01: c1.6,-2.4 r0.225
  circle w0.01: c1.6,-3.2 r0.225
  circle w0.01: c2.4,-3.2 r0.225
  circle w0.01: c3.2,-3.2 r0.225
  circle w0.01: c-1.6,-3.2 r0.225
  circle w0.01: c-2.4,-3.2 r0.225
  circle w0.01: c-3.2,-3.2 r0.225
  circle w0.01: c1.6,-4 r0.225
  circle w0.01: c2.4,-4 r0.225
  circle w0.01: c3.2,-4 r0.225
  circle w0.01: c-1.6,-4 r0.225
  circle w0.01: c-2.4,-4 r0.225
  circle w0.01: c-3.2,-4 r0.225
  circle w0.01: c1.6,-4.8 r0.225
  circle w0.01: c2.4,-4.8 r0.225
  circle w0.01: c3.2,-4.8 r0.225
  circle w0.01: c-1.6,-4.8 r0.225
  circle w0.01: c-2.4,-4.8 r0.225
  circle w0.01: c-3.2,-4.8 r0.225
  circle w0.01: c1.6,-5.6 r0.225
  circle w0.01: c2.4,-5.6 r0.225
  circle w0.01: c3.2,-5.6 r0.225
  circle w0.01: c-1.6,-5.6 r0.225
  circle w0.01: c-2.4,-5.6 r0.225
  circle w0.01: c-3.2,-5.6 r0.225
  circle w0.01: c-3.2,1.6 r0.225
  circle w0.01: c-2.4,1.6 r0.225
  circle w0.01: c-1.6,1.6 r0.225
  circle w0.01: c3.2,1.6 r0.225
  circle w0.01: c2.4,1.6 r0.225
  circle w0.01: c1.6,1.6 r0.225
  circle w0.01: c1.6,0.8 r0.225
  circle w0.01: c2.4,0.8 r0.225
  circle w0.01: c3.2,0.8 r0.225
  circle w0.01: c-1.6,0.8 r0.225
  circle w0.01: c-2.4,0.8 r0.225
  circle w0.01: c-3.2,0.8 r0.225
  circle w0.01: c1.6,0 r0.225
  circle w0.01: c2.4,0 r0.225
  circle w0.01: c3.2,0 r0.225
  circle w0.01: c-1.6,0 r0.225
  circle w0.01: c-2.4,0 r0.225
  circle w0.01: c-3.2,0 r0.225
  circle w0.01: c1.6,-0.8 r0.225
  circle w0.01: c2.4,-0.8 r0.225
  circle w0.01: c3.2,-0.8 r0.225
  circle w0.01: c-1.6,-0.8 r0.225
  circle w0.01: c-2.4,-0.8 r0.225
  circle w0.01: c-3.2,-0.8 r0.225
  circle w0.01: c1.6,-1.6 r0.225
  circle w0.01: c2.4,-1.6 r0.225
  circle w0.01: c3.2,-1.6 r0.225
  circle w0.01: c-1.6,-1.6 r0.225
  circle w0.01: c-2.4,-1.6 r0.225
  circle w0.01: c-3.2,-1.6 r0.225
  circle w0.01: c-3.2,2.4 r0.225
  circle w0.01: c-2.4,2.4 r0.225
  circle w0.01: c-1.6,2.4 r0.225
  circle w0.01: c3.2,2.4 r0.225
  circle w0.01: c2.4,2.4 r0.225
  circle w0.01: c1.6,2.4 r0.225
  circle w0.01: c-3.2,3.2 r0.225
  circle w0.01: c-2.4,3.2 r0.225
  circle w0.01: c-1.6,3.2 r0.225
  circle w0.01: c3.2,3.2 r0.225
  circle w0.01: c2.4,3.2 r0.225
  circle w0.01: c1.6,3.2 r0.225
  circle w0.01: c-3.2,4 r0.225
  circle w0.01: c-2.4,4 r0.225
  circle w0.01: c-1.6,4 r0.225
  circle w0.01: c3.2,4 r0.225
  circle w0.01: c2.4,4 r0.225
  circle w0.01: c1.6,4 r0.225
  circle w0.01: c-3.2,4.8 r0.225
  circle w0.01: c-2.4,4.8 r0.225
  circle w0.01: c-1.6,4.8 r0.225
  circle w0.01: c3.2,4.8 r0.225
  circle w0.01: c2.4,4.8 r0.225
  circle w0.01: c1.6,4.8 r0.225
  circle w0.01: c1.6,5.6 r0.225
  circle w0.01: c2.4,5.6 r0.225
  circle w0.01: c3.2,5.6 r0.225
  circle w0.01: c-1.6,5.6 r0.225
  circle w0.01: c-2.4,5.6 r0.225
  circle w0.01: c-3.2,5.6 r0.225
  lines w0.01: -4.05,-6.55 -4.05,6.55 4.05,6.55 4.05,-6.55 -4.05,-6.55
  text "'.Designator'" at -2,-0.5 h0.75
  text "A1" at -3.55,5.375 h0.75
M16-Top Courtyard:
  lines w0.01: -4.3,-6.8 4.075,-6.8 4.3,-6.8 4.3,6.8 -4.3,6.8 -4.3,-6.55 -4.3,-6.8
3D body: height 1, standoff 0, extent -4.05,-6.55 4.05,6.55
3D body "VFBGA90-1.STEP": height 1.1, standoff 0, extent -4,-6.5 4,6.5

## ICC_VFBGA96_9X13_P080 [mm]
height 1
pads (96):
  round 0.4 smd mask+0.05: A1(-3.2,6) A2(-2.4,6) A3(-1.6,6) A7(1.6,6) A8(2.4,6) A9(3.2,6) B1(-3.2,5.2) B2(-2.4,5.2) B3(-1.6,5.2) B7(1.6,5.2) B8(2.4,5.2) B9(3.2,5.2) C1(-3.2,4.4) C2(-2.4,4.4) C3(-1.6,4.4) C7(1.6,4.4) C8(2.4,4.4) C9(3.2,4.4) D1(-3.2,3.6) D2(-2.4,3.6) D3(-1.6,3.6) D7(1.6,3.6) D8(2.4,3.6) D9(3.2,3.6) E1(-3.2,2.8) E2(-2.4,2.8) E3(-1.6,2.8) E7(1.6,2.8) E8(2.4,2.8) E9(3.2,2.8) F1(-3.2,2) F2(-2.4,2) F3(-1.6,2) F7(1.6,2) F8(2.4,2) F9(3.2,2) G1(-3.2,1.2) G2(-2.4,1.2) G3(-1.6,1.2) G7(1.6,1.2) G8(2.4,1.2) G9(3.2,1.2) H1(-3.2,0.4) H2(-2.4,0.4) H3(-1.6,0.4) H7(1.6,0.4) H8(2.4,0.4) H9(3.2,0.4) J1(-3.2,-0.4) J2(-2.4,-0.4) J3(-1.6,-0.4) J7(1.6,-0.4) J8(2.4,-0.4) J9(3.2,-0.4) K1(-3.2,-1.2) K2(-2.4,-1.2) K3(-1.6,-1.2) K7(1.6,-1.2) K8(2.4,-1.2) K9(3.2,-1.2) L1(-3.2,-2) L2(-2.4,-2) L3(-1.6,-2) L7(1.6,-2) L8(2.4,-2) L9(3.2,-2) M1(-3.2,-2.8) M2(-2.4,-2.8) M3(-1.6,-2.8) M7(1.6,-2.8) M8(2.4,-2.8) M9(3.2,-2.8) N1(-3.2,-3.6) N2(-2.4,-3.6) N3(-1.6,-3.6) N7(1.6,-3.6) N8(2.4,-3.6) N9(3.2,-3.6) P1(-3.2,-4.4) P2(-2.4,-4.4) P3(-1.6,-4.4) P7(1.6,-4.4) P8(2.4,-4.4) P9(3.2,-4.4) R1(-3.2,-5.2) R2(-2.4,-5.2) R3(-1.6,-5.2) R7(1.6,-5.2) R8(2.4,-5.2) R9(3.2,-5.2) T1(-3.2,-6) T2(-2.4,-6) T3(-1.6,-6) T7(1.6,-6) T8(2.4,-6) T9(3.2,-6)
Top Overlay:
  circle w0.12: c-4.125,6.125 r0.225
  lines w0.12: -4.725,5.75 -4.725,6.725 -3.75,6.725 ; -1.275,-6.55 -1.275,6.55 ; 1.275,-6.55 1.275,6.55 ; -4.55,-6.55 4.55,-6.55 4.55,6.55 -4.55,6.55 -4.55,-6.55
M14-Top Assembly:
  circle w0.01: c-4.125,6.125 r0.225
  lines w0.01: -1.35,-6.55 -1.35,6.55 ; 1.35,-6.55 1.35,6.55 ; -4.55,-6.55 4.55,-6.55 4.55,6.55 -4.55,6.55 -4.55,-6.55
  text "'.Designator'" at -2,-0.5 h0.75
  text "A1" at -3.55,5.8 h0.75
M16-Top Courtyard:
  lines w0.01: -4.8,-6.8 -3.975,-6.8 4.8,-6.8 4.8,6.8 -4.6,6.8 -4.8,6.8 -4.8,-6.8
3D body "VFBGA96.STEP": height 1, standoff 0, extent -4,-6.5 4,6.5
3D body: height 1, standoff 0, extent -4.555,-6.555 4.555,6.555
